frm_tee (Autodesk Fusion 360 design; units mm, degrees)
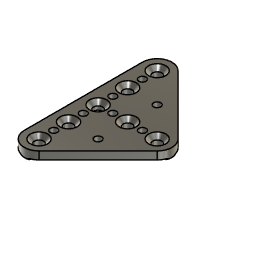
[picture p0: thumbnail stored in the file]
sketch "Sketch1" plane through (0, 0, 0) normal (0, 0, 1) x axis (1, 0, 0)
  line L1 (0, -36) -> (0, 0)
  line L2 (36, 0) -> (0, 0)
  line L3 (-9, -45) -> (-9, 0)
  line L4 (3.7279, -45) -> (-9, -45)
  line L5 (45, 0) -> (45, -3.7279)
  line L6 (10, 10) -> (-10, 10)
  line L7 (10, -10) -> (10, 10)
  line L8 (-10, -10) -> (10, -10)
  line L9 (-10, 10) -> (-10, -10)
  line L10 (-9, 9) -> (0, 0)
  line L11 (25.0711, -10.9289) -> (10.9289, -25.0711)
  line L12 (31.435, -17.2929) -> (25.0711, -10.9289)
  line L13 (17.2929, -31.435) -> (10.9289, -25.0711)
  line L14 (0, 0) -> (18, -18)
  line L15 (10, -38.7279) -> (10, -10)
  line L16 (38.7279, -10) -> (10, -10)
  line L17 (45, -3.7279) -> (3.7279, -45)
  line L18 (-9, 0) -> (0, 0)
  line L19 (45, 0) -> (36, 0)
  line L20 (3.7279, 45) -> (-9, 45)
  line L21 (45, 3.7279) -> (3.7279, 45)
  line L22 (-9, 45) -> (-9, 0)
  line L23 (45, 0) -> (45, 3.7279)
  line L24 (-3, -12) -> (-3, -45)
  line L25 (3, -12) -> (-3, -12)
  line L26 (3, -45) -> (3, -12)
  line L27 (12, 3) -> (45, 3)
  line L28 (12, -3) -> (12, 3)
  line L29 (45, -3) -> (12, -3)
  circle C1 centre (0, 0) radius 2.75
  circle C2 centre (18, 0) radius 2.75
  circle C3 centre (36, 0) radius 2.75
  circle C4 centre (0, -18) radius 2.75
  circle C5 centre (0, -36) radius 2.75
  circle C6 centre (0, 0) radius 5
  circle C7 centre (18, 0) radius 5
  circle C8 centre (36, 0) radius 5
  circle C9 centre (0, -18) radius 5
  circle C10 centre (0, -36) radius 5
  circle C11 centre (27, 0) radius 2.2
  circle C12 centre (27, 0) radius 2.5
  circle C13 centre (9, 0) radius 2.2
  circle C14 centre (9, 0) radius 2.5
  circle C15 centre (0, -9) radius 2.2
  circle C16 centre (0, -27) radius 2.2
  circle C17 centre (18, -18) radius 2.2
  circle C18 centre (0, 36) radius 2.75
  circle C19 centre (0, 27) radius 2.2
  circle C20 centre (0, 18) radius 2.75
  circle C21 centre (0, 9) radius 2.2
  circle C22 centre (18, 18) radius 2.2
  point P1 (0, 0)
  point P2 (0, 0)
  point P7 (0, 0)
  point P6 (0, -36)
  point P8 (0, -36)
  point P9 (0, 0)
  point P4 (36, 0)
  point P10 (36, 0)
  point P5 (0, -18)
  point P3 (18, 0)
  point P20 (10, 0)
  point P21 (0, -10)
  point P22 (18, 0)
  point P23 (36, 0)
  point P24 (0, -18)
  point P25 (0, -36)
  point P26 (27, 0)
  point P28 (9, 0)
  point P30 (0, 0)
  point P37 (18, -18)
  point P38 (0, 0)
  point P41 (18, -18)
  point P40 (38.7279, -10)
  point P36 (17.2929, -31.435)
  point P39 (10, -38.7279)
  point P35 (31.435, -17.2929)
  point P15 (0, 0)
  point P42 (0, 0)
  point P44 (36, 0)
  point P14 (-9, 9)
  point P11 (-9, -45)
  point P46 (-9, 45)
  point P12 (3.7279, -45)
  point P47 (3.7279, 45)
  point P13 (45, -3.7279)
  point P48 (45, 3.7279)
  point P43 (-9, 0)
  point P49 (-9, 0)
  point P55 (-3, -45)
  point P58 (3, -45)
  point P59 (45, 3)
  point P62 (45, -3)
  point P63 (12, 0)
  point P64 (0, -12)
  point P16 (-10, 10)
  point P17 (10, 10)
  point P19 (-10, -10)
  point P29 (9, 0)
  point P27 (27, 0)
  point P34 (25.0711, -10.9289)
  coincident P1 P2
  coincident P2 P7
  coincident P6 P8
  coincident P1 P9
  horizontal L2
  coincident P4 P10
  equal L1 L2
  coincident P5 L1
  coincident P3 L2
  equal C2 C3
  equal C2 C4
  equal C4 C5
  equal C1 C5
  vertical L3
  perpendicular L3 L4
  parallel L3 L5
  concentric C1 C6
  horizontal L6
  vertical L7
  horizontal L8
  vertical L9
  midpoint L7 P20
  midpoint L8 P21
  coincident L1 P21
  coincident L2 P20
  vertical L1
  equal C8 C9
  equal C7 C9
  equal C7 C10
  equal C6 C7
  coincident P3 P22
  coincident P4 P23
  coincident P5 P24
  coincident P6 P25
  coincident L2 P26
  concentric C11 C12
  coincident L2 P28
  concentric C13 C14
  equal C12 C14
  equal C11 C13
  coincident P1 P30
  symmetric C11 L10 C16
  symmetric C13 L10 C15
  perpendicular L11 L12
  perpendicular L11 L13
  midpoint L11 P37
  coincident P2 P38
  parallel L10 L14
  perpendicular L11 L14
  equal L6 L11
  perpendicular L4 L15
  perpendicular L15 L16
  coincident L14 P41
  equal C13 C17
  coincident P40 L17
  coincident P36 L17
  coincident P39 L17
  coincident P35 L17
  coincident P15 P42
  perpendicular L3 L18
  coincident P4 P44
  perpendicular L5 L19
  coincident L3 P14
  symmetric C4 L18 C20
  symmetric C5 L18 C18
  symmetric P11 L18 P46
  symmetric P12 L18 P47
  symmetric P13 L18 P48
  symmetric C15 L18 C21
  symmetric C16 L18 C19
  symmetric C17 L18 C22
  symmetric P43 L18 P49
  coincident L4 P55
  perpendicular L4 L24
  perpendicular L24 L25
  coincident L4 P58
  perpendicular L4 L26
  coincident L23 P59
  perpendicular L23 L27
  perpendicular L27 L28
  perpendicular L28 L29
  coincident L5 P62
  midpoint L28 P63
  midpoint L25 P64
  coincident L1 P64
  coincident L2 P63
  dimension "d1" diameter C1 = 5.5
  dimension "d3" distance P2 L3 = 9
  dimension "d4" diameter C6 = 10
  dimension "d5" distance P16 P17 = 20
  dimension "d6" distance P16 P19 = 20
  dimension "d7" distance P3 P15 = 18
  dimension "d8" distance P5 P15 = 18 (= "d7")
  dimension "d9" distance P3 P4 = 18 (= "d7")
  dimension "d12" distance P3 L7 = 8
  dimension "d13" distance L5 P16 = 55
  dimension "d16" diameter C13 = 4.4
  dimension "d17" diameter C14 = 5
  dimension "d18" distance P15 P29 = 9
  dimension "d19" distance P27 P29 = 18 (= "d7")
  dimension "d27" distance P34 P35 = 9
  dimension "d28" distance P15 P41 = 18
  dimension "d29" angle L5 L17 = 45
  dimension "d30" distance P4 L17 = 9 (= "d18")
  dimension "d31" angle L10 L18 = 45
  dimension "d33" distance P11 P46 = 90
  dimension "d34" distance P59 P62 = 6
  dimension "d35" distance P55 P58 = 6 (= "d34")
  dimension "d36" distance P17 L28 = 2
  dimension "d37" distance P19 L25 = 2
extrude "Extrude1" new body sketch "Sketch1" profile of C1 C2 C3 C4 C5 L2 L3 L4 L5 C11 C13 C15 C16 C17 L17 L18 L19 L24 L25 L26 L28 L29 along normal blind 4.7498
chamfer "Chamfer1" distance 2.5
extrude "Extrude2" add sketch "Sketch1" profile of C2 C3 C4 C5 L2 L4 L5 C11 C16 L19 L24 L25 L26 L28 L29 against normal blind 1.5
fillet "Fillet1" radius 9
fillet "Fillet3" ChordLen 3
chamfer "Chamfer2" distance 0.5
chamfer "Chamfer3" distance 1
mirror "Mirror1" mirrorStitchTolerance 0.1
named bodies: "frm_tee"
